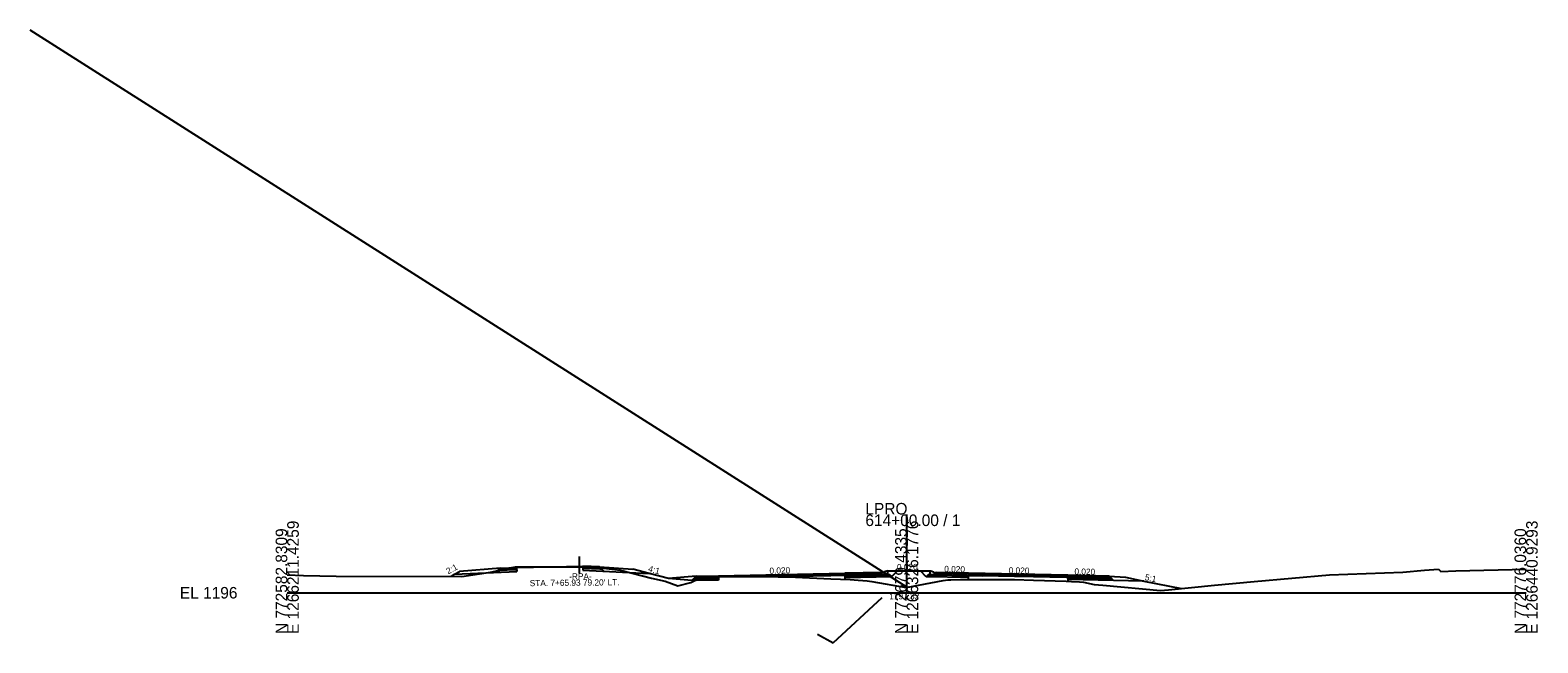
# Model space of a CAD drawing. Extents: x -3833 to 1267678, y -522 to 773248.
# Drawn here: x 1937.8 to 2302.8, y 4987.9 to 5136.4 of the extents above; entities that cross this region are included whole.
import ezdxf

# ---------------------------------------------------------------- set-up
doc = ezdxf.new("R2010")
doc.units = 0
for name, color, linetype in [('Exist Cross Section Cell', 7, 'Continuous'), ('Exist XS Center Line Elevation Label', 7, 'Continuous'), ('Exist XS Ground Line', 7, 'Continuous'), ('Prop CMT Corridor Surface Symbology Green', 7, 'Continuous'), ('Prop CMT DNC', 7, 'Continuous'), ('Prop CMT Pvmt Course 1', 7, 'Continuous'), ('Prop CMT Pvmt Course 2', 7, 'Continuous'), ('Prop CMT Pvmt Course 3', 7, 'Continuous'), ('Prop CMT Pvmt Course 4', 7, 'Continuous'), ('Prop CMT Shld Paved Course 1', 7, 'Continuous'), ('Prop CMT Shld Paved Course 2', 7, 'Continuous'), ('Prop CMT Shld Paved Course 4', 7, 'Continuous'), ('Prop CMT Slope Grass', 7, 'Continuous'), ('Prop CMT Subgrade Earthwork', 7, 'Continuous'), ('Prop Conc Curb and Gutter', 7, 'Continuous'), ('Prop Conc Island Cover', 7, 'Continuous'), ('Prop Corridor Mesh Bottom', 7, 'Continuous'), ('Prop XS Ditch Slope Text', 7, 'Continuous'), ('Prop XS Finish Grade', 7, 'Continuous'), ('Prop XS SE Text', 7, 'Continuous'), ('Prop XS Shear Point Element', 7, 'Continuous'), ('Scratch_Level_1', 7, 'Continuous'), ('Scratch_Level_5', 7, 'Continuous')]:
    doc.layers.add(name, color=color, linetype=linetype)

msp = doc.modelspace()

# ---------------------------------------------------------------- linework, layer by layer
at = {"layer": 'Exist Cross Section Cell'}
for p, q in [((2150, 5000), (2150, 5018.97)), ((2000, 5000), (2150, 5000)), ((2150, 5000), (2300, 5000))]:
    msp.add_line(p, q, dxfattribs=at)
at = {"layer": 'Exist XS Ground Line'}
for p, q in [((2049.23, 5005.01), (2053.6, 5005.97)), ((2053.6, 5005.97), (2054.37, 5006.11)), ((2054.37, 5006.11), (2055.27, 5006.25)), ((2055.27, 5006.25), (2055.87, 5006.25)), ((2055.87, 5006.25), (2072.36, 5006.27)), ((2072.36, 5006.27), (2073.46, 5006.22)), ((2073.46, 5006.22), (2073.92, 5006.32)), ((2073.92, 5006.32), (2077.35, 5005.91)), ((2077.35, 5005.91), (2080.63, 5005.5)), ((2080.63, 5005.5), (2081.06, 5005.41)), ((2081.06, 5005.41), (2088.19, 5003.55)), ((2270.17, 5005.01), (2275.43, 5005.47)), ((2275.43, 5005.47), (2278.79, 5005.68)), ((2278.79, 5005.68), (2279.38, 5005.19)), ((2282.99, 5005.3), (2300, 5005.74)), ((2000, 5004.32), (2003.98, 5004.19)), ((2003.98, 5004.19), (2011.82, 5004.06)), ((2011.82, 5004.06), (2042.3, 5003.98)), ((2042.3, 5003.98), (2049.23, 5005.01)), ((2088.19, 5003.55), (2091.51, 5002.83)), ((2091.51, 5002.83), (2094.6, 5001.71)), ((2094.6, 5001.71), (2097.73, 5002.51)), ((2097.73, 5002.51), (2099.95, 5003.53)), ((2099.95, 5003.53), (2103.22, 5003.76)), ((2103.22, 5003.76), (2104.33, 5003.83)), ((2104.33, 5003.83), (2109.1, 5003.92)), ((2109.1, 5003.92), (2111.69, 5003.97)), ((2111.69, 5003.97), (2118.85, 5003.83)), ((2118.85, 5003.83), (2123.11, 5003.75)), ((2123.11, 5003.75), (2131.61, 5003.39)), ((2131.61, 5003.39), (2136.32, 5003.18)), ((2136.32, 5003.18), (2138.22, 5003.08)), ((2138.22, 5003.08), (2139.36, 5003)), ((2139.36, 5003), (2140.44, 5002.87)), ((2140.44, 5002.87), (2141, 5002.8)), ((2141, 5002.8), (2141.6, 5002.69)), ((2141.6, 5002.69), (2149.89, 5001.3)), ((2149.89, 5001.3), (2158.83, 5002.95)), ((2158.83, 5002.95), (2159.96, 5003.13)), ((2159.96, 5003.13), (2160.69, 5003.16)), ((2160.69, 5003.16), (2163.02, 5003.21)), ((2163.02, 5003.21), (2164.32, 5003.24)), ((2164.32, 5003.24), (2168.55, 5003.22)), ((2168.55, 5003.22), (2176.09, 5003.2)), ((2176.09, 5003.2), (2180.72, 5003.08)), ((2180.72, 5003.08), (2188.63, 5002.84)), ((2188.63, 5002.84), (2189.95, 5002.74)), ((2189.95, 5002.74), (2191.84, 5002.61)), ((2191.84, 5002.61), (2192.81, 5002.54)), ((2192.81, 5002.54), (2195.4, 5002)), ((2195.4, 5002), (2197.52, 5001.81)), ((2197.52, 5001.81), (2211.47, 5000.57)), ((2213.37, 5000.71), (2224.51, 5001.85)), ((2224.51, 5001.85), (2234.13, 5002.72)), ((2234.13, 5002.72), (2252.36, 5004.33)), ((2252.36, 5004.33), (2270.17, 5005.01)), ((2279.38, 5005.19), (2282.99, 5005.3)), ((2211.47, 5000.57), (2213.37, 5000.71))]:
    msp.add_line(p, q, dxfattribs=at)
at = {"layer": 'Prop CMT Pvmt Course 1'}
for p, q in [((2055.62, 5006.16), (2067.62, 5006.4)), ((2055.62, 5006.16), (2055.62, 5006.16)), ((2067.62, 5006.4), (2071.62, 5006.48)), ((2067.62, 5006.4), (2067.62, 5006.4)), ((2071.62, 5006.48), (2071.62, 5006.48)), ((2104.42, 5004.13), (2135, 5004.74)), ((2135, 5004.49), (2104.42, 5003.88)), ((2104.42, 5003.88), (2104.42, 5004.13)), ((2104.42, 5004.13), (2104.42, 5004.13)), ((2135, 5004.74), (2135, 5004.74)), ((2135, 5004.74), (2135, 5004.74)), ((2135, 5004.74), (2135, 5004.49)), ((2135, 5004.49), (2135, 5004.49)), ((2189, 5004.26), (2165, 5004.74)), ((2165, 5004.74), (2165, 5004.74)), ((2165, 5004.74), (2165, 5004.74)), ((2165, 5004.74), (2165, 5004.49)), ((2165, 5004.49), (2165, 5004.49)), ((2189, 5004.01), (2189, 5004.26)), ((2189, 5004.26), (2189, 5004.26))]:
    msp.add_line(p, q, dxfattribs=at)
at = {"layer": 'Prop CMT Pvmt Course 2'}
for p, q in [((2143.91, 5004.67), (2135, 5004.49)), ((2135, 5004.49), (2135, 5004.49)), ((2135, 5004.49), (2135, 5004.16)), ((2135, 5004.15), (2143.91, 5004.33)), ((2135, 5004.16), (2135, 5004.16)), ((2135, 5004.16), (2135, 5004.15)), ((2150, 5004.79), (2150, 5004.79)), ((2150, 5004.79), (2150, 5004.79)), ((2150, 5004.46), (2150, 5004.46)), ((2150, 5004.46), (2150, 5004.46)), ((2165, 5004.49), (2157.22, 5004.64)), ((2157.22, 5004.31), (2168.25, 5004.09)), ((2165, 5004.49), (2165, 5004.49)), ((2165, 5004.15), (2165, 5004.15))]:
    msp.add_line(p, q, dxfattribs=at)
at = {"layer": 'Prop CMT Pvmt Course 3'}
for p, q in [((2145.93, 5004.37), (2143.91, 5004.33)), ((2143.91, 5004.33), (2143.91, 5004.33)), ((2146.38, 5003.93), (2145.93, 5004.37)), ((2154.92, 5004.06), (2155.2, 5004.35)), ((2155.2, 5004.35), (2157.22, 5004.31))]:
    msp.add_line(p, q, dxfattribs=at)
at = {"layer": 'Prop CMT Pvmt Course 4'}
for p, q in [((2143.91, 5004.33), (2135, 5004.15)), ((2135, 5004.15), (2135, 5004.16)), ((2135, 5004.16), (2135, 5004.16)), ((2135, 5004.16), (2135, 5004.16)), ((2135, 5004.16), (2135, 5003.24)), ((2135, 5003.7), (2146.38, 5003.93)), ((2135, 5003.32), (2135, 5003.32)), ((2135, 5003.32), (2135, 5003.32)), ((2150, 5004.46), (2150, 5004.46)), ((2150, 5004.46), (2150, 5004.46)), ((2155.2, 5004.35), (2154.75, 5003.9)), ((2155.71, 5004.34), (2155.2, 5004.35)), ((2165, 5003.7), (2165, 5004.15)), ((2165, 5004.15), (2165, 5004.15)), ((2165, 5004.15), (2165, 5004.15)), ((2165, 5003.32), (2165, 5003.32))]:
    msp.add_line(p, q, dxfattribs=at)
at = {"layer": 'Prop CMT Shld Paved Course 1'}
for p, q in [((2051.37, 5005.73), (2051.62, 5005.99)), ((2051.62, 5005.99), (2055.62, 5006.16)), ((2071.62, 5006.48), (2071.62, 5006.48)), ((2071.62, 5006.48), (2071.62, 5006.48)), ((2071.62, 5006.48), (2071.62, 5006.23)), ((2075.62, 5006.32), (2071.62, 5006.48)), ((2071.62, 5006.23), (2071.62, 5006.23)), ((2071.62, 5006.23), (2075.88, 5006.06)), ((2075.88, 5006.06), (2075.62, 5006.32)), ((2075.62, 5006.32), (2075.62, 5006.32)), ((2098.8, 5003.76), (2099.05, 5004.02)), ((2104.42, 5003.88), (2098.8, 5003.76)), ((2099.05, 5004.02), (2104.42, 5004.13)), ((2099.05, 5004.02), (2099.05, 5004.02)), ((2104.42, 5004.13), (2104.42, 5004.13)), ((2104.42, 5004.13), (2104.42, 5004.13)), ((2104.42, 5004.13), (2104.42, 5003.88)), ((2104.42, 5003.88), (2104.42, 5003.88)), ((2143.91, 5004.92), (2135, 5004.74)), ((2135, 5004.74), (2135, 5004.74)), ((2135, 5004.74), (2135, 5004.49)), ((2135, 5004.49), (2143.91, 5004.67)), ((2150, 5005.04), (2150, 5005.04)), ((2150, 5005.04), (2150, 5005.04)), ((2150, 5004.79), (2150, 5004.79)), ((2150, 5004.79), (2150, 5004.79)), ((2165, 5004.74), (2157.22, 5004.89)), ((2165, 5004.49), (2165, 5004.74)), ((2165, 5004.74), (2165, 5004.74)), ((2189, 5004.26), (2189, 5004.01)), ((2199, 5004.06), (2189, 5004.26)), ((2189, 5004.01), (2199.26, 5003.8)), ((2199.26, 5003.8), (2199, 5004.06))]:
    msp.add_line(p, q, dxfattribs=at)
at = {"layer": 'Prop CMT Shld Paved Course 2'}
for p, q in [((2051.04, 5005.39), (2051.37, 5005.73)), ((2055.63, 5005.58), (2051.04, 5005.39)), ((2051.37, 5005.73), (2055.62, 5005.91)), ((2071.62, 5006.23), (2071.62, 5006.23)), ((2071.62, 5006.23), (2071.62, 5006.23)), ((2075.88, 5006.06), (2071.62, 5006.23)), ((2071.62, 5005.9), (2071.62, 5005.9)), ((2076.22, 5005.71), (2075.88, 5006.06)), ((2075.88, 5006.06), (2075.88, 5006.06)), ((2098.46, 5003.42), (2098.8, 5003.76)), ((2104.43, 5003.54), (2098.46, 5003.42)), ((2098.8, 5003.76), (2104.42, 5003.88)), ((2098.8, 5003.76), (2098.8, 5003.76)), ((2104.42, 5003.88), (2111.69, 5004.02)), ((2111, 5003.96), (2104.42, 5003.83)), ((2104.42, 5003.83), (2104.42, 5003.88)), ((2104.42, 5003.88), (2104.42, 5003.88)), ((2104.42, 5003.88), (2104.42, 5003.88)), ((2104.42, 5003.88), (2104.42, 5003.88)), ((2104.42, 5003.88), (2104.42, 5003.88)), ((2104.42, 5003.88), (2104.43, 5003.54)), ((2104.42, 5003.54), (2104.42, 5003.54)), ((2111.69, 5003.97), (2111, 5003.96)), ((2111.69, 5004.02), (2118.85, 5004.16)), ((2118.74, 5003.83), (2111.69, 5003.97)), ((2118.85, 5003.83), (2118.74, 5003.83)), ((2118.74, 5003.83), (2118.74, 5003.83)), ((2118.85, 5004.16), (2123.11, 5004.25)), ((2118.85, 5004.16), (2118.85, 5004.16)), ((2123.11, 5003.92), (2118.85, 5003.83)), ((2118.85, 5003.83), (2118.85, 5003.83)), ((2123.11, 5004.25), (2131.61, 5004.42)), ((2123.11, 5004.25), (2123.11, 5004.25)), ((2131.61, 5004.09), (2123.11, 5003.92)), ((2123.11, 5003.92), (2123.11, 5003.92)), ((2131.61, 5004.42), (2135, 5004.49)), ((2131.61, 5004.42), (2131.61, 5004.42)), ((2135, 5004.15), (2131.61, 5004.09)), ((2131.61, 5004.09), (2131.61, 5004.09)), ((2135, 5004.49), (2135, 5004.49)), ((2135, 5004.49), (2135, 5004.49)), ((2135, 5004.49), (2135, 5004.15)), ((2135, 5004.15), (2135, 5004.15)), ((2165, 5004.15), (2165, 5004.49)), ((2165, 5004.49), (2165, 5004.49)), ((2165, 5004.49), (2165, 5004.49)), ((2165, 5004.49), (2168.55, 5004.42)), ((2165, 5004.15), (2165, 5004.15)), ((2176.09, 5003.93), (2168.25, 5004.09)), ((2168.55, 5004.42), (2168.55, 5004.42)), ((2168.55, 5004.42), (2176.09, 5004.27)), ((2168.55, 5004.08), (2168.55, 5004.08)), ((2176.09, 5004.27), (2176.09, 5004.27)), ((2176.09, 5004.27), (2180.72, 5004.17)), ((2180.72, 5003.84), (2176.09, 5003.93)), ((2176.09, 5003.93), (2176.09, 5003.93)), ((2180.72, 5004.17), (2180.72, 5004.17)), ((2180.72, 5004.17), (2188.63, 5004.01)), ((2188.63, 5003.68), (2180.72, 5003.84)), ((2180.72, 5003.84), (2180.72, 5003.84)), ((2188.63, 5004.01), (2189, 5004.01)), ((2189, 5003.67), (2188.63, 5003.68)), ((2189, 5004.01), (2189, 5004.01)), ((2189, 5004.01), (2189, 5004.01)), ((2189, 5004.01), (2189, 5003.67)), ((2189, 5004.01), (2189, 5003.68)), ((2199.26, 5003.8), (2189, 5004.01)), ((2189, 5003.68), (2199.59, 5003.47)), ((2189, 5003.67), (2189, 5003.67)), ((2199.59, 5003.47), (2199.26, 5003.8))]:
    msp.add_line(p, q, dxfattribs=at)
at = {"layer": 'Prop CMT Shld Paved Course 4'}
for p, q in [((2050.58, 5004.91), (2051.04, 5005.39)), ((2051.04, 5005.39), (2051.54, 5005.41)), ((2055.63, 5005.58), (2055.64, 5005.12)), ((2071.62, 5005.9), (2071.62, 5005.9)), ((2071.62, 5005.9), (2071.62, 5005.9)), ((2075.72, 5005.73), (2071.62, 5005.9)), ((2071.62, 5005.44), (2071.62, 5005.44)), ((2076.22, 5005.71), (2075.72, 5005.73)), ((2075.72, 5005.73), (2075.72, 5005.73)), ((2076.75, 5005.19), (2076.22, 5005.71)), ((2076.22, 5005.71), (2076.22, 5005.71)), ((2097.99, 5002.96), (2098.46, 5003.42)), ((2104.43, 5003.08), (2097.99, 5002.96)), ((2098.46, 5003.42), (2098.96, 5003.43)), ((2098.96, 5003.43), (2104.43, 5003.54)), ((2104.43, 5003.54), (2104.43, 5003.08)), ((2189, 5003.68), (2189, 5003.22)), ((2199.09, 5003.48), (2189, 5003.68)), ((2199.59, 5003.47), (2199.09, 5003.48)), ((2200.06, 5003), (2199.59, 5003.47))]:
    msp.add_line(p, q, dxfattribs=at)
at = {"layer": 'Prop CMT Slope Grass'}
for p, q in [((2051.62, 5005.99), (2041.71, 5005.19)), ((2075.62, 5006.32), (2083.66, 5005.68)), ((2087.65, 5004.67), (2083.66, 5005.68)), ((2040.54, 5004.49), (2041.71, 5005.19)), ((2099.05, 5004.02), (2092.34, 5003.48)), ((2145.43, 5005.35), (2147.79, 5005.34)), ((2153.33, 5005.33), (2155.71, 5005.32)), ((2199, 5004.06), (2203, 5003.74)), ((2203, 5003.74), (2207.43, 5002.85))]:
    msp.add_line(p, q, dxfattribs=at)
at = {"layer": 'Prop CMT Subgrade Earthwork'}
for p, q in [((2055.64, 5005.12), (2055.61, 5006.25)), ((2071.62, 5006.27), (2071.62, 5005.44)), ((2071.62, 5005.44), (2087.65, 5004.67)), ((2040.54, 5004.49), (2055.64, 5005.12)), ((2097.99, 5002.96), (2092.34, 5003.48)), ((2104.43, 5003.08), (2097.99, 5002.96)), ((2104.43, 5003.83), (2104.43, 5003.08)), ((2146.38, 5003.93), (2135, 5003.7)), ((2135, 5003.7), (2135, 5003.24)), ((2146.38, 5003.93), (2147.8, 5005.34)), ((2154.75, 5003.9), (2153.33, 5005.33)), ((2165, 5003.7), (2154.75, 5003.9)), ((2165, 5003.24), (2165, 5003.7)), ((2207.43, 5002.85), (2189, 5003.22)), ((2189, 5003.22), (2189, 5002.81))]:
    msp.add_line(p, q, dxfattribs=at)
at = {"layer": 'Prop Conc Curb and Gutter'}
for p, q in [((2144.66, 5004.93), (2143.91, 5004.92)), ((2143.91, 5004.92), (2143.91, 5004.92)), ((2143.91, 5004.92), (2143.91, 5004.33)), ((2143.91, 5004.92), (2143.91, 5004.92)), ((2143.91, 5004.33), (2145.41, 5004.36)), ((2143.91, 5004.33), (2143.91, 5004.33)), ((2143.91, 5004.33), (2143.91, 5004.33)), ((2143.91, 5004.33), (2143.91, 5004.33)), ((2144.67, 5004.93), (2144.66, 5004.93)), ((2145.42, 5005.34), (2144.67, 5005.1)), ((2144.67, 5005.1), (2144.67, 5005.1)), ((2144.67, 5005.1), (2144.67, 5004.93)), ((2145.41, 5004.36), (2145.43, 5004.36)), ((2145.43, 5005.35), (2145.42, 5005.34)), ((2145.43, 5005.33), (2145.43, 5005.35)), ((2145.43, 5004.36), (2145.43, 5005.33)), ((2155.71, 5005.14), (2155.71, 5005.32)), ((2155.71, 5005.32), (2155.83, 5005.28)), ((2155.71, 5004.34), (2155.71, 5005.14)), ((2155.94, 5004.34), (2155.71, 5004.34)), ((2155.83, 5005.28), (2156.47, 5005.07)), ((2157.22, 5004.31), (2155.94, 5004.34)), ((2156.47, 5005.07), (2156.47, 5005.06)), ((2156.47, 5005.06), (2156.47, 5004.91)), ((2156.47, 5004.91), (2156.53, 5004.91)), ((2156.53, 5004.91), (2157.22, 5004.89)), ((2157.22, 5004.89), (2157.22, 5004.89)), ((2157.22, 5004.89), (2157.22, 5004.31))]:
    msp.add_line(p, q, dxfattribs=at)
at = {"layer": 'Prop Conc Island Cover'}
msp.add_line((2145.43, 5005.35), (2145.43, 5005.1), dxfattribs=at)
at = {"layer": 'Prop Corridor Mesh Bottom'}
for p, q in [((2135, 5004.74), (2135, 5004.49)), ((2189, 5004.26), (2189, 5004.01))]:
    msp.add_line(p, q, dxfattribs=at)
at = {"layer": 'Prop XS Finish Grade'}
for p, q in [((2039.7, 5003.98), (2040.54, 5004.49)), ((2092.34, 5003.48), (2087.65, 5004.67)), ((2147.8, 5005.34), (2150.4, 5005.34)), ((2150.4, 5005.34), (2153.33, 5005.33)), ((2207.43, 5002.85), (2216.53, 5001.03))]:
    msp.add_line(p, q, dxfattribs=at)
at = {"layer": 'Prop XS Shear Point Element'}
msp.add_line((2070.8, 5004.73), (2070.8, 5008.75), dxfattribs=at)
at = {"layer": 'Scratch_Level_1'}
msp.add_line((2150, 5001.32), (1937.75, 5136.38), dxfattribs=at)
at = {"layer": 'Scratch_Level_5'}
for p, q in [((2132.2, 4987.85), (2144.06, 4998.88)), ((2128.42, 4989.96), (2132.2, 4987.85))]:
    msp.add_line(p, q, dxfattribs=at)

# ---------------------------------------------------------------- texts
at = {"layer": 'Exist Cross Section Cell'}
for s, p in [('LPRO', (2140, 5018.97)), ('614+00.00 / 1', (2140, 5016.17)), ('EL 1196', (1974, 4998.6))]:
    msp.add_text(s, height=2.8, dxfattribs=at).set_placement(p)
for s, p in [('E 1266211.4259', (2002.8, 4990)), ('E 1266326.1776', (2152.8, 4990)), ('E 1266440.9293', (2302.8, 4990)), ('N 772582.8309', (2000, 4990)), ('N 772679.4335', (2150, 4990)), ('N 772776.0360', (2300, 4990))]:
    msp.add_text(s, height=2.8, rotation=90, dxfattribs=at).set_placement(p)
at = {"layer": 'Exist XS Center Line Elevation Label'}
msp.add_text('1197.32', height=1.5, dxfattribs=at).set_placement((2145.79, 4998.4))
at = {"layer": 'Prop CMT Corridor Surface Symbology Green'}
msp.add_text('X', height=0.00025, dxfattribs=at).set_placement((2071.24, 5006.3))
at = {"layer": 'Prop CMT DNC'}
for p in [(2111, 5004.26), (2135, 5004.74), (2135, 5004.74), (2144.67, 5004.93), (2150, 5005.04), (2156.47, 5004.91), (2165, 5004.74), (2165, 5004.74), (2189, 5004.26), (2189, 5004.26), (2199, 5004.06), (2210, 5002.34)]:
    msp.add_text('X', height=0.00025, dxfattribs=at).set_placement(p)
at = {"layer": 'Prop XS Ditch Slope Text'}
for s, rotation, p in [('2:1', 28.1814, (2038.98, 5004.45)), ('4:1', 344.67, (2087.31, 5005.19)), ('5:1', 348.3376, (2207.57, 5003.09))]:
    msp.add_text(s, height=1.5, rotation=rotation, dxfattribs=at).set_placement(p)
at = {"layer": 'Prop XS SE Text'}
for s, rotation, p in [('0.020', 1.397, (2116.79, 5004.59)), ('0.020', 0.2693, (2147.65, 5005.48)), ('0.020', 358.8542, (2159.09, 5005.03)), ('0.020', 358.8542, (2174.69, 5004.69)), ('0.020', 358.8542, (2190.61, 5004.42)), ("STA. 7+65.93 79.20' LT.", 0.5826, (2058.73, 5001.59)), ('-RPA-', 0.5826, (2068.28, 5003.2))]:
    msp.add_text(s, height=1.5, rotation=rotation, dxfattribs=at).set_placement(p)

doc.saveas('drawing.dxf')
